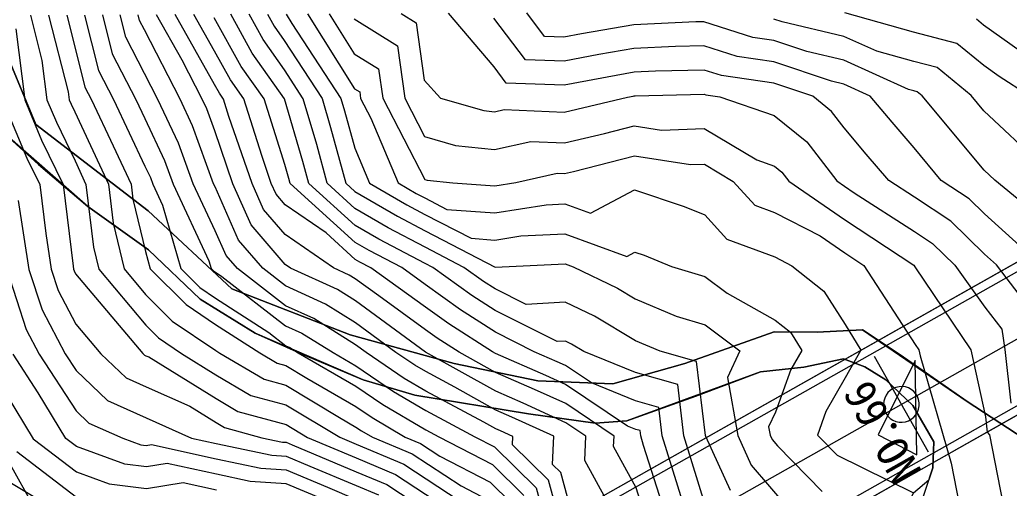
# Model space of a CAD drawing. Extents: x 42655 to 43811, y -141820 to -141156.
# Drawn here: x 42764.1 to 42836.1, y -141591.3 to -141557.3 of the extents above; entities that cross this region are included whole.
import ezdxf

# ---------------------------------------------------------------- set-up
doc = ezdxf.new("R2010")
doc.units = 0
for name, color, linetype in [('D-BMK-HTXT_1', 7, 'Continuous'), ('D-BMK_1', 7, 'Continuous'), ('D-STR-STR2トンネル', 7, 'Continuous'), ('ZE_HICN', 7, 'Continuous'), ('ZE_LWCN', 7, 'Continuous'), ('地形', 7, 'Continuous'), ('現況道路ﾊｯﾁ', 7, 'Continuous'), ('着色', 7, 'Continuous')]:
    doc.layers.add(name, color=color, linetype=linetype)

msp = doc.modelspace()

# ---------------------------------------------------------------- linework, layer by layer
at = {"layer": 'D-BMK-HTXT_1'}
for p, q in [((42777.191, -141614.053), (42738.344, -141545.264)), ((42830.192, -141588.716), (42826.259, -141581.75))]:
    msp.add_line(p, q, dxfattribs=at)
msp.add_lwpolyline([(42826.925, -141585.233), (42826.946, -141585.465), (42827.008, -141585.69), (42827.11, -141585.9), (42827.247, -141586.088), (42827.415, -141586.249), (42827.609, -141586.378), (42827.824, -141586.469), (42828.051, -141586.521), (42828.284, -141586.532), (42828.515, -141586.5), (42828.736, -141586.428), (42828.942, -141586.318), (42829.124, -141586.172), (42829.277, -141585.997), (42829.397, -141585.797), (42829.479, -141585.579), (42829.52, -141585.349), (42829.52, -141585.116), (42829.479, -141584.887), (42829.397, -141584.669), (42829.277, -141584.469), (42829.124, -141584.293), (42828.942, -141584.148), (42828.736, -141584.037), (42828.515, -141583.965), (42828.284, -141583.934), (42828.051, -141583.945), (42827.824, -141583.996), (42827.609, -141584.088), (42827.415, -141584.216), (42827.246, -141584.378), (42827.109, -141584.566), (42827.008, -141584.776), (42826.946, -141585.001), (42826.925, -141585.233)], dxfattribs=at)
at = {"layer": 'D-BMK_1'}
msp.add_line((42932.715, -141526.226), (42777.191, -141614.053), dxfattribs=at)
at = {"layer": 'D-STR-STR2トンネル'}
for p, q in [((43087.053, -141433.469), (42774.793, -141609.807)), ((43087.348, -141433.992), (42775.088, -141610.33)), ((43091.527, -141441.393), (42779.268, -141617.731)), ((43091.822, -141441.915), (42779.563, -141618.253))]:
    msp.add_line(p, q, dxfattribs=at)
at = {"layer": 'ZE_HICN'}
for points in [[(42766.173, -141556.915), (42767.601, -141562.496), (42767.674, -141563.07), (42767.81, -141563.396), (42768.082, -141563.959), (42770.536, -141569.22), (42770.873, -141572.046), (42771.669, -141575.377), (42773.232, -141577.239), (42775.178, -141579.178), (42778.339, -141581.319), (42778.633, -141581.507), (42781.857, -141583.407), (42783.439, -141583.835), (42787.35, -141586.19), (42788.542, -141586.881), (42788.934, -141587.148), (42789.734, -141587.618), (42792.63, -141588.827), (42796.195, -141591.165), (42798.142, -141592.175)], [(42804.982, -141595.845), (42803.44, -141590.197), (42802.85, -141589.615), (42802.942, -141587.557), (42799.883, -141586.156), (42798.713, -141585.646), (42795.728, -141583.985), (42793.611, -141582.851), (42792.826, -141582.389), (42791.44, -141581.448), (42788.507, -141579.301), (42786.329, -141577.938), (42783.406, -141576.602), (42781.766, -141575.33), (42780.001, -141573.28), (42778.284, -141569.407), (42778.18, -141569.184), (42776.656, -141564.975), (42775.742, -141563.033), (42773.142, -141557.988), (42772.79, -141557.307), (42772.684, -141556.884)], [(42814.011, -141592.78), (42812.4, -141587.513), (42811.956, -141583.791), (42808.876, -141582.918), (42805.128, -141581.384), (42804.23, -141580.841), (42803.777, -141580.624), (42803.172, -141580.66), (42798.679, -141578.404), (42796.978, -141577.314), (42794.121, -141575.273), (42793.575, -141574.989), (42790.193, -141573.215), (42788.473, -141572.211), (42785.107, -141569.152), (42784.674, -141567.567), (42783.342, -141562.997), (42780.995, -141559.67), (42779.427, -141556.853)], [(42786.596, -141556.82), (42788.415, -141559.728), (42790.186, -141560.828), (42790.485, -141562.964), (42793.546, -141568.862), (42793.713, -141568.911), (42795.583, -141569.103), (42798.637, -141569.326), (42800.162, -141569.082), (42803.183, -141568.417), (42803.721, -141568.44), (42804.359, -141568.288), (42808.803, -141567.14), (42812.872, -141567.785), (42813.894, -141567.749), (42815.995, -141569.008), (42817.566, -141570.733), (42818.999, -141571.264), (42822.305, -141572.973), (42824.101, -141574.211), (42825.486, -141575.126), (42829.22, -141580.876), (42829.488, -141581.27), (42829.58, -141581.701), (42831.839, -141589.503), (42832.621, -141593.48)], [(42839.357, -141572.475), (42835.032, -141568.919), (42834.249, -141568.19), (42829.741, -141562.781), (42829.38, -141562.485), (42829.134, -141562.42), (42828.742, -141562.312), (42824.035, -141560.197), (42821.345, -141559.565), (42818.94, -141558.754), (42817.407, -141558.532), (42813.846, -141557.395), (42813.256, -141557.41), (42808.759, -141557.614), (42804.949, -141558.279), (42803.674, -141558.516), (42802.252, -141558.469), (42800.963, -141556.753)], [(42763.128, -141575.417), (42764.55, -141579.778), (42765.487, -141581.569), (42768.183, -141585.714), (42769.11, -141586.597), (42771.585, -141587.703), (42772.887, -141588.176), (42773.283, -141588.225), (42773.67, -141588.162), (42778.376, -141589.198), (42781.627, -141589.885), (42783.468, -141590.004), (42786.473, -141591.266), (42788.566, -141592.148)], [(42829.352, -141588.906), (42829.225, -141582.029), (42826.544, -141587.447), (42829.352, -141588.906)]]:
    msp.add_lwpolyline(points, dxfattribs=at)
at = {"layer": 'ZE_LWCN'}
for points in [[(42764.851, -141556.921), (42765.691, -141560.205), (42766.059, -141563.078), (42766.741, -141564.703), (42768.099, -141567.521), (42768.894, -141569.227), (42769.44, -141573.799), (42769.819, -141575.386), (42773.242, -141579.463), (42774.18, -141580.398), (42775.838, -141581.52), (42778.348, -141583.076), (42780.899, -141584.578), (42783.446, -141585.269), (42787.367, -141587.629), (42788.548, -141588.127), (42792.018, -141589.575), (42797.757, -141593.339)], [(42767.494, -141556.909), (42768.059, -141559.118), (42768.822, -141562.159), (42769.289, -141563.063), (42770.879, -141566.429), (42772.177, -141569.212), (42772.306, -141570.294), (42773.218, -141574.106), (42773.577, -141575.368), (42776.176, -141577.957), (42778.331, -141579.417), (42781.557, -141581.494), (42782.815, -141582.235), (42783.433, -141582.402), (42784.959, -141583.321), (42788.535, -141585.397), (42789.713, -141586.196), (42792.112, -141587.607), (42793.242, -141588.079), (42794.633, -141588.992), (42798.304, -141590.894), (42799.864, -141592.432)], [(42768.8, -141556.903), (42769.814, -141560.946), (42770.905, -141563.055), (42773.189, -141567.892), (42773.584, -141568.732), (42773.755, -141569.205), (42774.474, -141570.742), (42775.79, -141575.358), (42777.174, -141576.737), (42778.322, -141577.515), (42782.2, -141580.012), (42783.426, -141580.962), (42783.739, -141581.105), (42784.34, -141581.481), (42788.528, -141583.912), (42790.491, -141585.245), (42793.631, -141587.091), (42794.573, -141587.596), (42798.465, -141589.613), (42800.758, -141591.873)], [(42770.095, -141556.897), (42770.806, -141559.733), (42772.52, -141563.048), (42773.172, -141564.43), (42774.608, -141567.479), (42775.23, -141569.198), (42777.84, -141574.781), (42778.002, -141575.348), (42778.172, -141575.517), (42778.313, -141575.613), (42778.789, -141575.919), (42783.419, -141579.508), (42784.603, -141580.049), (42786.871, -141581.469), (42788.521, -141582.427), (42791.27, -141584.293), (42793.624, -141585.678), (42797.182, -141587.584), (42798.626, -141588.332), (42801.652, -141591.314), (42802.691, -141595.12)], [(42803.836, -141595.482), (42802.546, -141590.755), (42799.922, -141588.169), (42799.949, -141587.571), (42799.059, -141587.163), (42798.719, -141587.015), (42797.851, -141586.532), (42793.618, -141584.265), (42792.048, -141583.341), (42789.274, -141581.458), (42788.514, -141580.901), (42785.466, -141578.994), (42783.412, -141578.055), (42779.909, -141575.339), (42779.093, -141574.391), (42778.299, -141572.6), (42776.705, -141569.191), (42775.632, -141566.227), (42774.132, -141563.04), (42773.157, -141561.149), (42771.798, -141558.52), (42771.389, -141556.89)], [(42806.742, -141592.163), (42805.188, -141589.317), (42805.266, -141587.546), (42803.805, -141586.567), (42800.707, -141585.148), (42798.706, -141584.276), (42793.605, -141581.438), (42788.499, -141577.7), (42787.193, -141576.882), (42783.777, -141575.321), (42783.399, -141575.061), (42780.909, -141572.17), (42779.583, -141569.178), (42778.265, -141565.337), (42777.681, -141563.722), (42777.352, -141563.025), (42775.886, -141560.18), (42774.019, -141556.878)], [(42809.678, -141593.688), (42808.915, -141591.295), (42807.284, -141588.307), (42807.318, -141587.536), (42803.799, -141585.179), (42801.531, -141584.141), (42798.7, -141582.907), (42796.039, -141581.426), (42794.448, -141580.407), (42793.597, -141579.799), (42790.194, -141577.345), (42788.492, -141576.099), (42788.056, -141575.827), (42786.917, -141575.306), (42783.388, -141572.884), (42781.818, -141571.059), (42780.981, -141569.171), (42779.301, -141564.278), (42778.905, -141563.018), (42778.605, -141562.593), (42778.249, -141561.954), (42775.376, -141556.872)], [(42811.21, -141593.681), (42809.469, -141588.215), (42809.259, -141587.527), (42809.213, -141587.144), (42808.896, -141587.053), (42808.297, -141586.809), (42803.792, -141583.791), (42802.356, -141583.133), (42798.693, -141581.537), (42798.474, -141581.415), (42795.291, -141579.376), (42793.589, -141578.16), (42789.614, -141575.294), (42788.829, -141574.882), (42788.485, -141574.681), (42786.373, -141572.762), (42783.378, -141570.706), (42782.726, -141569.949), (42782.379, -141569.165), (42781.681, -141567.133), (42780.384, -141563.011), (42779.402, -141561.618), (42778.238, -141559.527), (42776.733, -141556.866)], [(42815.787, -141591.501), (42813.986, -141587.558), (42813.97, -141587.505), (42813.327, -141582.114), (42810.661, -141581.358), (42808.866, -141580.604), (42805.895, -141578.806), (42803.764, -141577.784), (42800.918, -141577.956), (42798.672, -141576.828), (42797.821, -141576.283), (42796.393, -141575.262), (42793.569, -141573.794), (42790.874, -141572.381), (42788.468, -141570.976), (42786.454, -141569.146), (42785.684, -141566.332), (42784.71, -141562.991), (42783.332, -141560.88), (42781.792, -141558.696), (42780.763, -141556.847)], [(42782.098, -141556.841), (42782.589, -141557.721), (42783.323, -141558.762), (42786.078, -141562.985), (42786.693, -141565.098), (42787.8, -141569.139), (42788.462, -141569.741), (42791.556, -141571.547), (42793.564, -141572.6), (42798.664, -141575.251), (42803.751, -141575.009), (42804.337, -141575.225), (42807.559, -141576.771), (42808.851, -141577.553), (42811.848, -141578.812), (42813.949, -141579.441), (42816.478, -141581.331), (42815.573, -141583.281), (42816.318, -141587.495), (42817.302, -141589.649), (42819.964, -141592.767)], [(42783.455, -141556.834), (42783.882, -141557.517), (42787.446, -141562.978), (42787.703, -141563.863), (42788.447, -141566.581), (42789.527, -141569.131), (42792.238, -141570.713), (42793.558, -141571.406), (42796.912, -141573.149), (42798.655, -141573.276), (42800.524, -141572.977), (42803.741, -141572.824), (42808.237, -141574.48), (42808.836, -141574.162), (42809.509, -141574.386), (42811.5, -141575.192), (42813.932, -141575.92), (42815.557, -141577.134), (42819.035, -141579.101), (42820.145, -141579.974), (42820.986, -141581.31), (42820.191, -141582.694), (42819.066, -141585.792), (42818.566, -141586.871), (42818.674, -141587.484), (42818.817, -141587.797), (42819.203, -141588.25), (42822.463, -141591.568)], [(42785.025, -141556.827), (42788.427, -141562.264), (42788.814, -141562.504), (42788.88, -141562.972), (42789.624, -141564.406), (42791.621, -141569.122), (42792.92, -141569.88), (42793.552, -141570.211), (42795.159, -141571.047), (42798.646, -141571.301), (42802.384, -141570.703), (42803.731, -141570.639), (42805.613, -141571.332), (42808.815, -141569.631), (42812.417, -141570.831), (42813.911, -141571.435), (42815.534, -141573.218), (42819.014, -141574.508), (42820.258, -141575.151), (42822.59, -141576.986), (42824.125, -141579.426), (42825.279, -141581.29), (42824.143, -141583.3), (42822.737, -141585.748), (42822.113, -141587.468), (42823.552, -141588.933), (42829.094, -141591.668)], [(42791.834, -141556.795), (42792.928, -141557.475), (42793.513, -141561.646), (42794.685, -141562.945), (42797.843, -141563.861), (42798.611, -141563.94), (42799.321, -141563.784), (42803.7, -141563.974), (42808.303, -141562.881), (42808.72, -141562.804), (42808.783, -141562.793), (42808.856, -141562.789), (42813.87, -141562.662), (42813.996, -141562.702), (42815.013, -141562.85), (42818.966, -141564.225), (42821.337, -141566.122), (42823.519, -141568.973), (42824.078, -141569.359), (42824.794, -141569.832), (42829.182, -141572.654), (42830.494, -141573.518), (42832.109, -141575.096), (42834.296, -141578.167), (42835.521, -141579.767), (42835.75, -141581.241), (42836.193, -141585.144)], [(42837.18, -141577.739), (42835.145, -141575.081), (42834.278, -141574.293), (42831.822, -141571.894), (42829.17, -141570.149), (42827.314, -141568.955), (42825.668, -141567.024), (42824.058, -141565.107), (42823.144, -141563.913), (42821.776, -141562.818), (42818.955, -141561.867), (42815.133, -141561.312), (42813.862, -141560.906), (42810.323, -141560.996), (42808.775, -141561.066), (42807.463, -141561.295), (42803.691, -141561.997), (42799.48, -141561.859), (42798.596, -141560.682), (42795.266, -141556.779)], [(42837.442, -141562.745), (42835.348, -141561.386), (42834.214, -141560.578), (42832.255, -141558.97), (42829.114, -141558.141), (42824.111, -141556.756)], [(42812.743, -141593.674), (42811.953, -141591.195), (42810.83, -141587.52), (42810.584, -141585.467), (42808.886, -141584.986), (42805.687, -141583.677), (42803.786, -141582.404), (42803.18, -141582.126), (42801.516, -141581.401), (42798.686, -141579.98), (42796.134, -141578.345), (42793.582, -141576.521), (42791.865, -141575.283), (42789.511, -141574.048), (42788.479, -141573.446), (42783.761, -141569.158), (42783.664, -141568.802), (42783.365, -141567.775), (42781.863, -141563.004), (42780.198, -141560.644), (42778.227, -141557.101)], [(42788.404, -141557.192), (42791.557, -141559.151), (42792.09, -141562.957), (42793.532, -141565.734), (42795.778, -141566.386), (42798.624, -141566.679), (42801.252, -141566.1), (42803.71, -141566.207), (42806.628, -141565.514), (42808.793, -141564.955), (42810.775, -141565.269), (42813.882, -141565.16), (42817.698, -141567.446), (42818.983, -141567.894), (42819.53, -141568.331), (42820.034, -141568.989), (42824.089, -141571.785), (42829.12, -141575.11), (42829.194, -141575.222), (42833.285, -141581.253), (42834.333, -141586.142), (42834.46, -141587.262), (42834.626, -141587.448), (42836.189, -141595.396)], [(42838.345, -141575.066), (42834.264, -141571.359), (42833.15, -141570.271), (42831.124, -141568.937), (42829.153, -141566.573), (42827.563, -141564.707), (42825.96, -141562.799), (42824.043, -141561.937), (42823.147, -141561.727), (42818.948, -141560.31), (42816.27, -141559.922), (42813.854, -141559.151), (42811.789, -141559.203), (42808.767, -141559.34), (42806.206, -141559.787), (42803.683, -141560.257), (42800.866, -141560.164), (42798.58, -141557.12)], [(42838.381, -141567.748), (42834.229, -141563.881), (42833.299, -141562.765), (42830.817, -141560.728), (42829.124, -141560.281), (42826.427, -141559.534), (42824.027, -141558.456), (42819.543, -141557.404), (42818.933, -141557.198)], [(42836.867, -141559.528), (42834.2, -141557.63), (42833.692, -141557.213)], [(42763.782, -141557.915), (42764.443, -141563.085), (42765.671, -141566.011), (42767.225, -141569.235), (42767.956, -141575.179), (42767.989, -141575.394), (42768.031, -141575.521), (42768.137, -141575.724), (42773.038, -141581.534), (42773.158, -141581.648), (42773.253, -141581.691), (42773.462, -141581.784), (42778.356, -141584.816), (42779.94, -141585.75), (42783.453, -141586.702), (42785.012, -141587.64), (42788.552, -141589.132), (42791.407, -141590.323), (42796.475, -141593.648)], [(42762.992, -141563.482), (42764.602, -141567.319), (42765.529, -141569.243), (42765.965, -141572.79), (42766.369, -141575.402), (42766.87, -141576.94), (42768.154, -141579.392), (42769.972, -141581.548), (42771.808, -141583.298), (42773.263, -141583.948), (42776.454, -141585.374), (42778.364, -141586.557), (42778.982, -141586.922), (42781.692, -141587.656), (42783.191, -141587.973), (42783.459, -141587.99), (42783.895, -141588.173), (42788.557, -141590.137), (42790.795, -141591.071), (42794.769, -141593.678)], [(42763.974, -141570.401), (42764.749, -141575.409), (42765.71, -141578.359), (42767.386, -141581.56), (42768.17, -141582.765), (42770.459, -141584.947), (42773.274, -141586.205), (42776.573, -141587.68), (42778.371, -141588.075), (42782.409, -141588.929), (42783.463, -141588.997), (42785.184, -141589.72), (42788.562, -141591.143), (42790.183, -141591.819)], [(42787.762, -141592.812), (42783.473, -141591.011), (42780.845, -141590.841), (42778.381, -141590.32), (42774.815, -141589.535), (42773.291, -141589.786), (42771.729, -141589.592), (42768.195, -141588.307), (42767.432, -141587.722), (42765.417, -141584.389), (42763.588, -141581.577)], [(42763.089, -141584.482), (42765.054, -141587.733), (42768.204, -141590.147), (42770.572, -141591.008), (42773.298, -141591.346), (42775.959, -141590.909), (42778.387, -141591.443)], [(42763.866, -141588.656), (42768.213, -141591.987)], [(42763.118, -141590.747), (42768.094, -141593.729)]]:
    msp.add_lwpolyline(points, dxfattribs=at)
at = {"layer": '地形'}
for points in [[(42837.144, -141587.724), (42833.01, -141585.023), (42828.127, -141581.633), (42825.396, -141579.813), (42822.086, -141579.979), (42818.971, -141579.959), (42812.466, -141582.266), (42807.219, -141583.734), (42801.763, -141583.524), (42795.677, -141582.266), (42788.122, -141580.169), (42779.518, -141576.814), (42773.432, -141571.152), (42765.248, -141564.861), (42762.52, -141558.361), (42761.68, -141552.489), (42761.051, -141548.295), (42760.673, -141546.269), (42757.757, -141542.445), (42754.295, -141538.985), (42751.379, -141536.163), (42747.279, -141532.43), (42744.09, -141530.063)], [(42762.749, -141565.341), (42765.439, -141567.772), (42769.021, -141570.839), (42773.455, -141573.992), (42777.207, -141577.571), (42781.215, -141580.042), (42784.626, -141581.576), (42789.06, -141583.45), (42792.812, -141584.558), (42801.083, -141585.921), (42805.944, -141586.603), (42808.246, -141586.432), (42813.277, -141584.643), (42817.967, -141582.853), (42821.122, -141582.513), (42824.022, -141581.916), (42825.557, -141582.512), (42827.091, -141583.45), (42829.053, -141585.324), (42830.588, -141587.966), (42830.502, -141589.841), (42830.222, -141590.72)], [(42829.307, -141645.174), (42828.068, -141631.344), (42829.376, -141614.303), (42827.167, -141599.099), (42827.549, -141594.892), (42829.094, -141591.668), (42830.222, -141590.72)]]:
    msp.add_lwpolyline(points, dxfattribs=at)
at = {"layer": '現況道路ﾊｯﾁ'}
for points in [[(42762.52, -141558.361), (42765.248, -141564.861), (42773.432, -141571.152), (42779.518, -141576.814), (42788.122, -141580.169), (42795.677, -141582.266), (42801.763, -141583.524), (42807.219, -141583.734), (42812.466, -141582.266), (42818.971, -141579.959), (42822.086, -141579.979), (42825.396, -141579.813), (42833.01, -141585.023), (42837.144, -141587.724)], [(42827.08, -141600.278), (42830.502, -141589.841), (42830.588, -141587.966), (42829.053, -141585.324), (42827.091, -141583.45), (42825.557, -141582.512), (42824.022, -141581.916), (42821.122, -141582.513), (42817.967, -141582.853), (42808.246, -141586.432), (42805.944, -141586.603), (42801.083, -141585.921), (42792.812, -141584.558), (42789.06, -141583.45), (42781.215, -141580.042), (42777.207, -141577.571), (42773.455, -141573.992), (42769.021, -141570.839), (42762.749, -141565.341)]]:
    msp.add_lwpolyline(points, dxfattribs=at)
at = {"layer": '着色'}
msp.add_lwpolyline([(42779.563, -141618.253), (43091.823, -141441.915), (43087.053, -141433.469), (42774.793, -141609.807)], close=True, dxfattribs=at)

# ---------------------------------------------------------------- texts
at = {"layer": 'D-BMK-HTXT_1'}
msp.add_text('NO.66', height=2.3065, rotation=119.45336, dxfattribs=at).set_placement((42829.748, -141590.115))

doc.saveas('drawing.dxf')
